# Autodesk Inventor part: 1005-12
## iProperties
Created: 2007-03
Part Number: 1005-12
Document SubType Name: Modeling
Designer: Andy Moles
Material: Steel
Mass: 0.0966438 g
Surface Area: 0.487907 cm^2
Volume: 0.0123113 cm^3
Density: 7.85 g/cm^3
Author: Andy Moles
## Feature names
1. Base1
